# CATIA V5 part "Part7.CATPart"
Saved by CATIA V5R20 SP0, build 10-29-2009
Part number: 3JT9.5X2X13.5
Revision: ANY
Definition: UNKNOWN
Nomenclature: 3JT9.5X2X13.5
Source: Unknown
Bounding box of the stored display mesh (mm): x -6.581 to 6.581, y -1 to 1, z -6.75 to 6.75
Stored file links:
  C:\Users\Utente\Desktop\IO LAVORO\3D X SITO CF\CUMSA\3D files PW\pw081225\pw081225_injection\Part7.CATPart
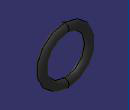
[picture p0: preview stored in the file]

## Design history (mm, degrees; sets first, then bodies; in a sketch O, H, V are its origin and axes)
Body1 "Revolución1" (main body)
  Solid1: solid without history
